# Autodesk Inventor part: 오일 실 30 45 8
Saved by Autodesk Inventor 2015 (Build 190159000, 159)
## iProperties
Created: 2026-07
Part Number: 오일 실 30 45 8
Material: 일반
Document SubType Name: Modeling
Designer: user
Density: 1 g/cm^3
Appearance: 기본값
Author: user
Author: jhkim
Creation Date: 2026-07-01
Sending System: Autodesk Inventor 2027
Preprocessor: ST-DEVELOPER v20.1
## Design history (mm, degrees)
node "오일 실 30 45 81"
body "Solid1"
node "기준1"
